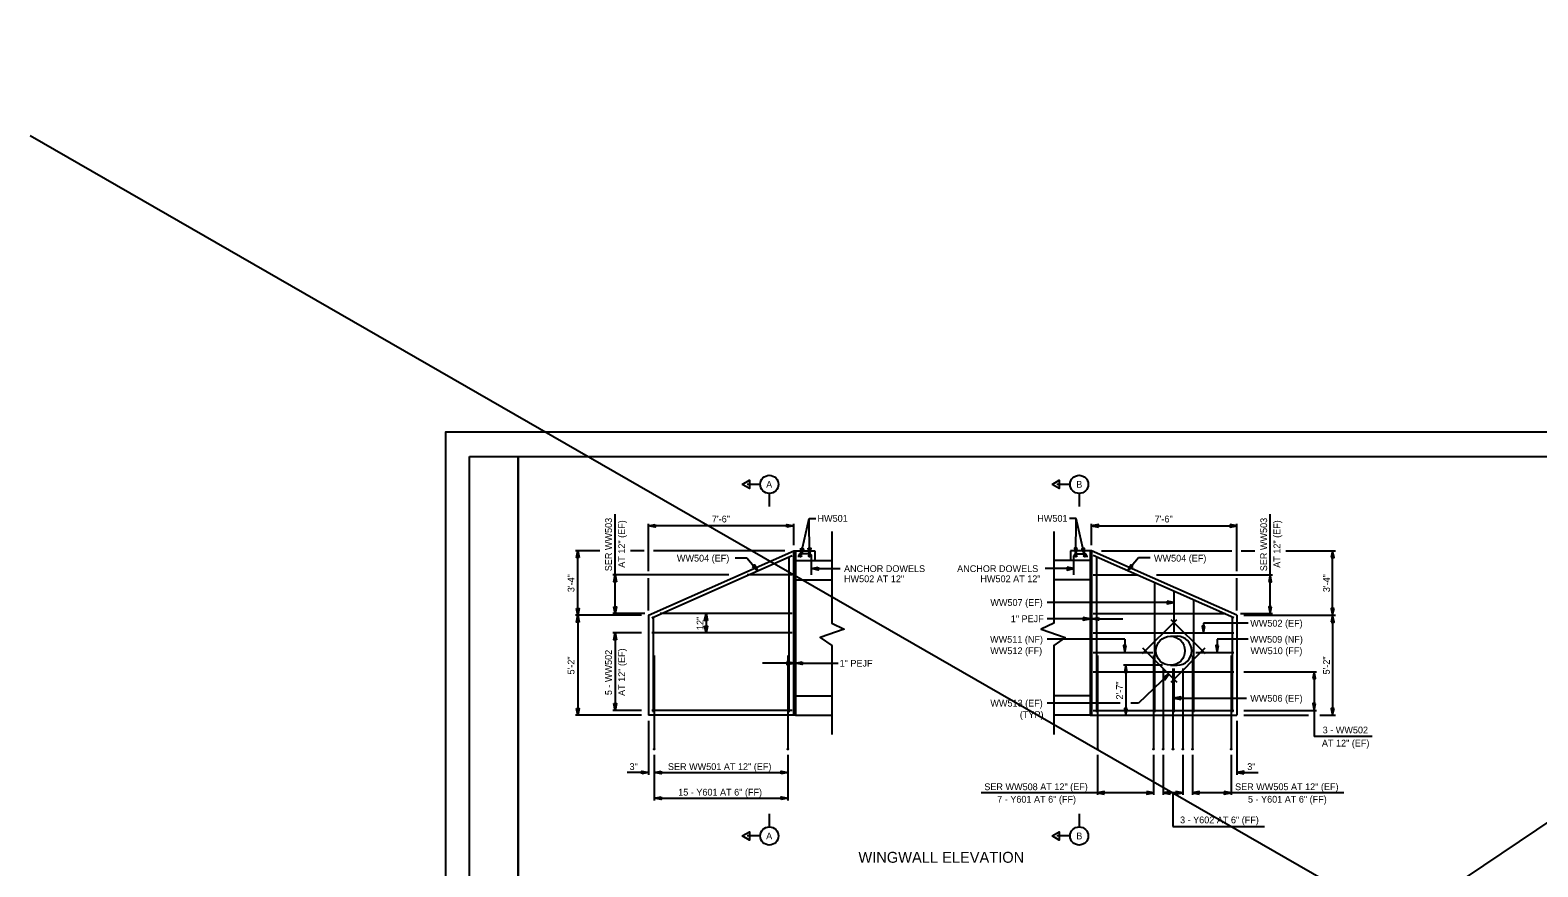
# Model space of a CAD drawing. Extents: x -375 to 456, y -77 to 177.
# Drawn here: x -25.4 to 52.4, y 133.6 to 176.8 of the extents above; entities that cross this region are included whole.
import ezdxf

# ---------------------------------------------------------------- set-up
doc = ezdxf.new("R2010")
doc.units = 0
for name, color, linetype in [('BR_P_Gen_Text', 7, 'Continuous'), ('BR_P_Slab_Reinforcing', 7, 'Continuous'), ('BR_P_Sub_Reinforcing', 7, 'Continuous'), ('DR_P_Culvert', 7, 'Continuous'), ('SH_Border', 7, 'Continuous'), ('SH_Cut_Line', 7, 'Continuous'), ('SH_Data', 7, 'Continuous'), ('ST_Details', 7, 'Continuous'), ('TX_P_1', 7, 'Continuous')]:
    doc.layers.add(name, color=color, linetype=linetype)

msp = doc.modelspace()

# ---------------------------------------------------------------- linework, layer by layer
at = {"layer": 'BR_P_Gen_Text'}
for points in [[(6.856, 151.313), (6.856, 151.173), (6.506, 151.243)], [(13.656, 151.173), (13.656, 151.313), (14.006, 151.243)], [(29.734, 151.173), (29.734, 151.313), (29.384, 151.243)], [(36.534, 151.313), (36.534, 151.173), (36.884, 151.243)], [(2.93, 149.609), (2.79, 149.609), (2.86, 149.959)], [(14.378, 150.093), (14.514, 150.061), (14.366, 149.736)], [(14.75, 150.087), (14.89, 150.088), (14.822, 149.737)], [(28.64, 150.087), (28.5, 150.088), (28.567, 149.737)], [(29.012, 150.093), (28.875, 150.061), (29.023, 149.736)], [(41.756, 149.609), (41.896, 149.609), (41.826, 149.959)], [(4.862, 148.359), (4.722, 148.359), (4.792, 148.709)], [(11.87, 149.14), (11.977, 149.231), (12.149, 148.918)], [(15.273, 149.102), (15.273, 148.962), (14.923, 149.032)], [(28.117, 149.102), (28.117, 148.962), (28.467, 149.032)], [(31.52, 149.14), (31.413, 149.231), (31.24, 148.918)], [(38.527, 148.359), (38.667, 148.359), (38.597, 148.709)], [(33.284, 147.353), (33.284, 147.213), (33.634, 147.283)], [(2.79, 146.975), (2.93, 146.975), (2.86, 146.625)], [(2.93, 146.275), (2.79, 146.275), (2.86, 146.625)], [(4.722, 147.059), (4.862, 147.059), (4.792, 146.709)], [(9.546, 146.359), (9.406, 146.359), (9.476, 146.709)], [(28.95, 146.512), (28.95, 146.372), (29.3, 146.442)], [(29.734, 146.512), (29.734, 146.372), (29.384, 146.442)], [(38.667, 147.059), (38.527, 147.059), (38.597, 146.709)], [(41.896, 146.975), (41.756, 146.975), (41.826, 146.625)], [(41.756, 146.275), (41.896, 146.275), (41.826, 146.625)], [(4.862, 145.359), (4.722, 145.359), (4.792, 145.709)], [(9.406, 146.059), (9.546, 146.059), (9.476, 145.709)], [(35.231, 146.059), (35.091, 146.059), (35.161, 145.709)], [(31.161, 145.059), (31.021, 145.059), (31.091, 144.709)], [(35.93, 145.059), (35.79, 145.059), (35.86, 144.709)], [(13.656, 144.217), (13.656, 144.077), (14.006, 144.147)], [(14.439, 144.217), (14.439, 144.077), (14.089, 144.147)], [(31.072, 143.692), (31.212, 143.692), (31.142, 144.042)], [(33.061, 143.392), (33.158, 143.291), (33.362, 143.584)], [(40.796, 143.359), (40.936, 143.359), (40.866, 143.709)], [(2.79, 141.809), (2.93, 141.809), (2.86, 141.459)], [(4.722, 142.059), (4.862, 142.059), (4.792, 141.709)], [(31.212, 141.809), (31.072, 141.809), (31.142, 141.459)], [(33.984, 142.266), (33.984, 142.406), (33.634, 142.336)], [(40.936, 142.059), (40.796, 142.059), (40.866, 141.709)], [(41.896, 141.809), (41.756, 141.809), (41.826, 141.459)], [(6.156, 138.427), (6.156, 138.567), (6.506, 138.497)], [(7.156, 138.567), (7.156, 138.427), (6.806, 138.497)], [(13.356, 138.427), (13.356, 138.567), (13.706, 138.497)], [(37.234, 138.427), (37.234, 138.567), (36.884, 138.497)], [(7.156, 137.245), (7.156, 137.105), (6.806, 137.175)], [(13.356, 137.105), (13.356, 137.245), (13.706, 137.175)], [(30.034, 137.385), (30.034, 137.525), (29.684, 137.455)], [(32.234, 137.525), (32.234, 137.385), (32.584, 137.455)], [(33.434, 137.385), (33.434, 137.525), (33.084, 137.455)], [(33.734, 137.525), (33.734, 137.385), (34.084, 137.455)], [(34.934, 137.385), (34.934, 137.525), (34.584, 137.455)], [(36.234, 137.525), (36.234, 137.385), (36.584, 137.455)]]:
    msp.add_lwpolyline(points, close=True, dxfattribs=at)
at = {"layer": 'BR_P_Slab_Reinforcing'}
for p, q in [((6.673, 146.484), (13.923, 149.706)), ((13.756, 149.665), (13.756, 141.625)), ((36.717, 146.484), (29.467, 149.706)), ((29.634, 149.665), (29.634, 141.625)), ((13.923, 148.709), (11.604, 148.709)), ((29.467, 148.709), (31.786, 148.709)), ((32.634, 148.332), (32.634, 141.625)), ((33.634, 147.887), (33.634, 145.703)), ((34.634, 147.443), (34.634, 141.625)), ((6.756, 146.554), (6.756, 141.625)), ((13.923, 146.709), (7.104, 146.709)), ((29.467, 146.709), (36.286, 146.709)), ((32.005, 144.643), (33.776, 146.414)), ((33.479, 146.414), (35.251, 144.641)), ((36.634, 146.554), (36.634, 141.625)), ((13.923, 145.709), (6.673, 145.709)), ((29.467, 145.709), (36.717, 145.709)), ((32.005, 144.94), (33.778, 143.168)), ((33.481, 143.168), (35.251, 144.938)), ((6.806, 144.539), (6.806, 139.709)), ((13.706, 144.539), (13.706, 139.709)), ((29.467, 144.709), (32.538, 144.709)), ((29.684, 144.539), (29.684, 139.709)), ((32.584, 144.539), (32.584, 139.709)), ((34.584, 144.539), (34.584, 139.709)), ((34.766, 144.709), (36.717, 144.709)), ((36.584, 144.539), (36.584, 139.709)), ((29.467, 143.709), (36.717, 143.709)), ((33.084, 143.877), (33.084, 139.709)), ((33.584, 143.877), (33.584, 139.709)), ((33.634, 143.881), (33.634, 141.625)), ((34.084, 143.877), (34.084, 139.709)), ((13.923, 141.709), (6.673, 141.709)), ((29.467, 141.709), (36.717, 141.709))]:
    msp.add_line(p, q, dxfattribs=at)
for centre in [(14.356, 149.692), (14.823, 149.692), (28.567, 149.692), (29.034, 149.692)]:
    msp.add_circle(centre, 0.0452, dxfattribs=at)
at = {"layer": 'BR_P_Sub_Reinforcing'}
for p, q in [((14.256, 149.692), (14.256, 149.629)), ((14.823, 149.792), (14.356, 149.792)), ((14.923, 148.709), (14.923, 149.692)), ((28.467, 148.709), (28.467, 149.692)), ((28.567, 149.792), (29.034, 149.792)), ((29.134, 149.692), (29.134, 149.629))]:
    msp.add_line(p, q, dxfattribs=at)
for centre in [(6.806, 139.709), (13.706, 139.709), (29.684, 139.709), (32.584, 139.709), (33.084, 139.709), (33.584, 139.709), (34.084, 139.709), (34.584, 139.709), (36.584, 139.709)]:
    msp.add_circle(centre, 0.025, dxfattribs=at)
for centre, start, end in [((14.356, 149.692), 90, 180), ((14.823, 149.692), 360, 90), ((28.567, 149.692), 90, 180), ((29.034, 149.692), 0, 90)]:
    msp.add_arc(centre, 0.1, start, end, dxfattribs=at)
at = {"layer": 'DR_P_Culvert'}
for p, q in [((6.506, 146.625), (14.006, 149.959)), ((14.006, 149.959), (14.006, 141.459)), ((14.006, 149.959), (14.089, 149.959)), ((14.089, 149.959), (15.089, 149.959)), ((14.089, 149.959), (14.089, 141.459)), ((14.089, 149.459), (15.966, 149.459)), ((15.089, 149.959), (15.089, 149.459)), ((29.3, 149.459), (27.424, 149.459)), ((29.3, 149.959), (28.3, 149.959)), ((28.3, 149.959), (28.3, 149.459)), ((29.3, 149.959), (29.3, 141.459)), ((29.384, 149.959), (29.3, 149.959)), ((29.384, 149.959), (29.384, 141.459)), ((36.884, 146.625), (29.384, 149.959)), ((14.089, 148.459), (15.966, 148.459)), ((29.3, 148.459), (27.424, 148.459)), ((6.506, 146.625), (6.506, 141.459)), ((36.884, 146.625), (36.884, 141.459)), ((33.451, 145.542), (33.805, 145.542)), ((33.451, 144.042), (33.805, 144.042)), ((14.089, 142.459), (15.966, 142.459)), ((29.3, 142.459), (27.424, 142.459)), ((14.089, 141.459), (6.506, 141.459)), ((14.089, 141.459), (15.966, 141.459)), ((29.3, 141.459), (27.424, 141.459)), ((29.3, 141.459), (36.884, 141.459))]:
    msp.add_line(p, q, dxfattribs=at)
for points in [[(15.966, 150.959), (15.966, 146.224), (16.602, 145.906), (15.374, 145.473), (15.966, 145.064), (15.966, 140.459)], [(27.424, 150.959), (27.424, 146.224), (26.787, 145.906), (28.015, 145.473), (27.424, 145.064), (27.424, 140.459)]]:
    msp.add_lwpolyline(points, dxfattribs=at)
for points in [[(14.089, 141.459), (14.006, 141.459), (14.006, 149.959), (14.089, 149.959)], [(29.3, 141.459), (29.384, 141.459), (29.384, 149.959), (29.3, 149.959)]]:
    msp.add_lwpolyline(points, close=True, dxfattribs=at)
msp.add_circle((33.451, 144.792), 0.75, dxfattribs=at)
msp.add_arc((33.805, 144.792), 0.75, 270, 90, dxfattribs=at)
at = {"layer": 'SH_Border'}
for points in [[(-2.726, 154.831), (-0.226, 154.831), (-0.226, 102.331), (-2.726, 102.331)], [(-0.226, 154.831), (79.774, 154.831), (79.774, 102.331), (-0.226, 102.331)]]:
    msp.add_lwpolyline(points, close=True, dxfattribs=at)
at = {"layer": 'SH_Cut_Line'}
msp.add_lwpolyline([(-3.976, 101.081), (81.024, 101.081), (81.024, 156.081), (-3.976, 156.081)], close=True, dxfattribs=at)
at = {"layer": 'ST_Details'}
for p, q in [((12.276, 153.384), (11.596, 153.384)), ((28.271, 153.384), (27.591, 153.384)), ((12.745, 152.914), (12.745, 152.247)), ((28.74, 152.914), (28.74, 152.247)), ((12.745, 136.363), (12.745, 135.696)), ((28.74, 136.363), (28.74, 135.696)), ((12.276, 135.227), (11.596, 135.227)), ((28.271, 135.227), (27.591, 135.227))]:
    msp.add_line(p, q, dxfattribs=at)
for points in [[(11.347, 153.384), (11.713, 153.595), (11.713, 153.172)], [(27.342, 153.384), (27.708, 153.595), (27.708, 153.172)], [(11.347, 135.227), (11.713, 135.438), (11.713, 135.015)], [(27.342, 135.227), (27.708, 135.438), (27.708, 135.015)]]:
    msp.add_lwpolyline(points, close=True, dxfattribs=at)
for centre in [(12.745, 153.384), (28.74, 153.384), (12.745, 135.227), (28.74, 135.227)]:
    msp.add_circle(centre, 0.469, dxfattribs=at)
at = {"layer": 'TX_P_1'}
for p, q in [((113.747, 176.845), (-13.713, 91.11)), ((-25.414, 171.408), (108.315, 94.455)), ((4.792, 146.709), (4.792, 151.849)), ((38.597, 146.709), (38.597, 151.849)), ((6.506, 148.899), (6.506, 151.344)), ((14.006, 151.243), (6.506, 151.243)), ((14.006, 150.238), (14.006, 151.344)), ((14.366, 149.736), (14.809, 151.628)), ((14.822, 149.737), (14.809, 151.628)), ((14.809, 151.628), (15.143, 151.628)), ((28.58, 151.628), (28.247, 151.628)), ((28.567, 149.737), (28.58, 151.628)), ((29.023, 149.736), (28.58, 151.628)), ((29.384, 150.238), (29.384, 151.344)), ((29.384, 151.243), (36.884, 151.243)), ((36.884, 148.899), (36.884, 151.344)), ((3.987, 149.959), (2.731, 149.959)), ((2.86, 146.625), (2.86, 149.959)), ((6.281, 149.959), (5.58, 149.959)), ((13.554, 149.959), (6.772, 149.959)), ((10.988, 149.586), (11.584, 149.586)), ((11.584, 149.586), (12.149, 148.918)), ((29.888, 149.959), (36.618, 149.959)), ((31.806, 149.586), (31.24, 148.918)), ((32.402, 149.586), (31.806, 149.586)), ((37.108, 149.959), (37.81, 149.959)), ((39.402, 149.959), (41.973, 149.959)), ((41.826, 146.625), (41.826, 149.959)), ((10.657, 148.709), (4.667, 148.709)), ((14.923, 149.032), (16.402, 149.032)), ((28.467, 149.032), (26.988, 149.032)), ((32.733, 148.709), (38.723, 148.709)), ((6.506, 146.868), (6.506, 148.536)), ((36.884, 146.868), (36.884, 148.536)), ((33.634, 147.283), (27.087, 147.283)), ((6.153, 146.625), (2.731, 146.625)), ((2.86, 146.625), (2.86, 141.459)), ((6.318, 146.709), (4.667, 146.709)), ((9.476, 146.709), (9.476, 145.709)), ((29.3, 146.442), (27.087, 146.442)), ((29.384, 146.442), (30.989, 146.442)), ((37.072, 146.709), (38.723, 146.709)), ((37.237, 146.625), (41.973, 146.625)), ((41.826, 146.625), (41.826, 141.459)), ((6.153, 145.709), (4.667, 145.709)), ((4.792, 145.709), (4.792, 141.709)), ((37.464, 146.213), (35.161, 146.213)), ((35.161, 146.213), (35.161, 145.709)), ((31.091, 145.382), (27.087, 145.382)), ((31.091, 145.382), (31.091, 144.709)), ((37.464, 145.382), (35.86, 145.382)), ((35.86, 145.382), (35.86, 144.709)), ((14.006, 144.147), (12.401, 144.147)), ((14.089, 144.147), (16.303, 144.147)), ((33.034, 144.042), (31.023, 144.042)), ((31.142, 144.042), (31.142, 141.459)), ((33.362, 143.584), (31.799, 142.083)), ((37.237, 143.709), (40.992, 143.709)), ((40.866, 143.709), (40.866, 140.358)), ((6.153, 141.709), (4.667, 141.709)), ((30.864, 142.083), (27.087, 142.083)), ((31.799, 142.083), (31.4, 142.083)), ((33.634, 142.336), (37.377, 142.336)), ((37.237, 141.709), (40.992, 141.709)), ((6.153, 141.459), (2.731, 141.459)), ((6.506, 141.179), (6.506, 138.386)), ((36.884, 141.179), (36.884, 138.386)), ((37.237, 141.459), (40.583, 141.459)), ((41.17, 141.459), (41.973, 141.459)), ((43.873, 140.358), (40.866, 140.358)), ((6.806, 139.422), (6.806, 137.054)), ((13.706, 139.422), (13.706, 137.054)), ((29.684, 139.422), (29.684, 137.35)), ((32.584, 139.422), (32.584, 137.35)), ((33.084, 139.422), (33.084, 137.35)), ((34.084, 139.422), (34.084, 137.35)), ((34.584, 139.422), (34.584, 137.35)), ((36.584, 139.422), (36.584, 137.35)), ((6.506, 138.497), (5.409, 138.497)), ((6.806, 138.497), (13.706, 138.497)), ((36.884, 138.497), (37.981, 138.497)), ((6.806, 137.175), (13.706, 137.175)), ((32.584, 137.455), (23.682, 137.455)), ((34.084, 137.455), (33.084, 137.455)), ((33.584, 137.455), (33.584, 135.715)), ((42.403, 137.455), (34.584, 137.455)), ((33.584, 135.715), (38.302, 135.715))]:
    msp.add_line(p, q, dxfattribs=at)

# ---------------------------------------------------------------- texts
at = {"layer": 'SH_Data'}
msp.add_text('WINGWALL ELEVATION', height=0.56461, dxfattribs=at).set_placement((17.344, 133.841))
at = {"layer": 'TX_P_1'}
for s, p in [('A', (12.581, 153.209)), ('B', (28.59, 153.209)), ('HW501', (15.232, 151.453)), ('HW501', (26.578, 151.453)), ('7\'-6"', (9.781, 151.418)), ('7\'-6"', (32.635, 151.418)), ('WW504 (EF)', (7.974, 149.397)), ('WW504 (EF)', (32.602, 149.397)), ('ANCHOR DOWELS', (16.6, 148.857)), ('HW502 AT 12"', (16.6, 148.332)), ('ANCHOR DOWELS', (22.441, 148.857)), ('HW502 AT 12"', (23.641, 148.332)), ('WW507 (EF)', (24.156, 147.108)), ('1" PEJF', (25.209, 146.267)), ('WW502 (EF)', (37.573, 146.038)), ('WW511 (NF)', (24.142, 145.207)), ('WW509 (NF)', (37.559, 145.207)), ('WW512 (FF)', (24.151, 144.616)), ('WW510 (FF)', (37.586, 144.616)), ('1" PEJF', (16.373, 143.972)), ('WW506 (EF)', (37.573, 142.161)), ('WW513 (EF)', (24.156, 141.908)), ('(TYP)', (25.678, 141.318)), ('3 - WW502', (41.312, 140.524)), ('AT 12" (EF)', (41.27, 139.845)), ('3"', (5.529, 138.633)), ('SER WW501 AT 12" (EF)', (7.511, 138.633)), ('3"', (37.417, 138.633)), ('SER WW508 AT 12" (EF)', (23.844, 137.591)), ('SER WW505 AT 12" (EF)', (36.789, 137.591)), ('15 - Y601 AT 6" (FF)', (8.041, 137.311)), ('7 - Y601 AT 6" (FF)', (24.51, 136.947)), ('5 - Y601 AT 6" (FF)', (37.454, 136.947)), ('3 - Y602 AT 6" (FF)', (33.948, 135.88)), ('A', (12.581, 135.052)), ('B', (28.59, 135.052))]:
    msp.add_text(s, height=0.35, dxfattribs=at).set_placement(p)
for s, p in [('SER WW503', (4.617, 148.899)), ('AT 12" (EF)', (5.297, 149.077)), ('SER WW503', (38.443, 148.899)), ('AT 12" (EF)', (39.122, 149.077)), ('3\'-4"', (2.685, 147.817)), ('3\'-4"', (41.684, 147.817)), ('12"', (9.345, 145.861)), ('5 - WW502', (4.617, 142.499)), ('AT 12" (EF)', (5.297, 142.458)), ('5\'-2"', (2.685, 143.567)), ('5\'-2"', (41.684, 143.567)), ('2\'-7"', (31, 142.275))]:
    msp.add_text(s, height=0.35, rotation=90, dxfattribs=at).set_placement(p)

doc.saveas('drawing.dxf')
